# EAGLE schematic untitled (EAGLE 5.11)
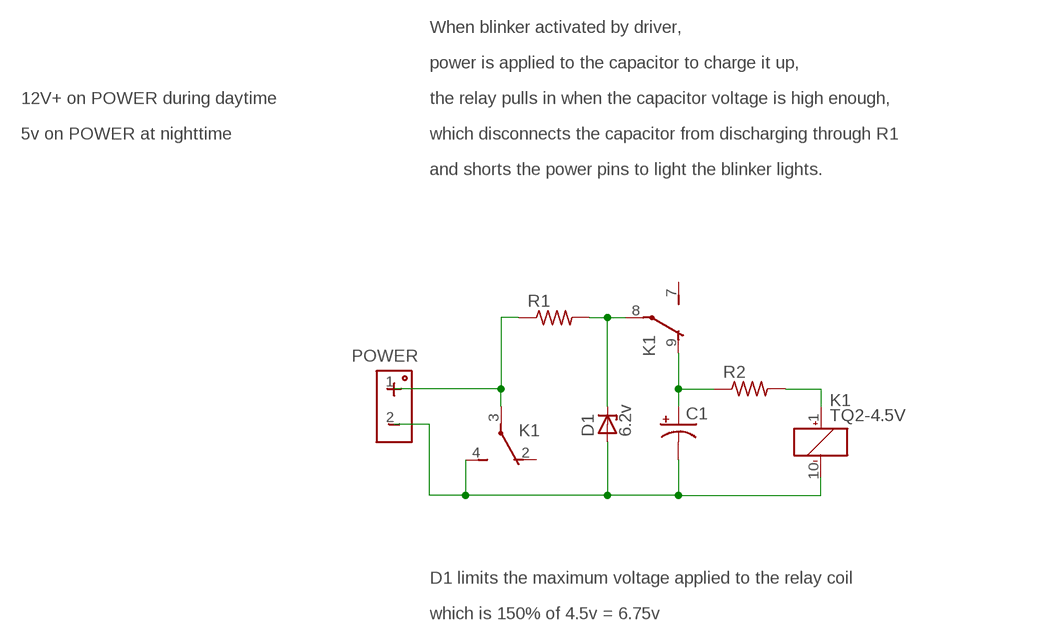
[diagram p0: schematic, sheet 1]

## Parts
C1  CPOL-USE2.5-5  [E2,5-5]
D1  6.2v  ZENER-DIODEZD-7.5  [ZDIO-7.5]
K1  TQ2-4.5V  [TQ2]
POWER  HEADER-POWER  [HEADER-POWER]
R1  R-US_0411/12  [0411/12]
R2  R-US_0411/12  [0411/12]

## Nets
N$1: K1.3(1:P) POWER.1 R1.1
N$2: C1.+ K1.9(2:O) R2.1
N$3: C1.- D1.A K1.4(1:S) K1.10(_:-) POWER.2
N$4: K1.1(_:+) R2.2
N$5: D1.C K1.8(2:P) R1.2
Unconnected: K1.2(1:O) K1.7(2:S)

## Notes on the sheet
- When blinker activated by driver,
- power is applied to the capacitor to charge it up,
- 12V+ on POWER during daytime | the relay pulls in when the capacitor voltage is high enough,
- 5v on POWER at nighttime | which disconnects the capacitor from discharging through R1
- and shorts the power pins to light the blinker lights.
- D1 limits the maximum voltage applied to the relay coil
- which is 150% of 4.5v = 6.75v

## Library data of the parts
C1 = resistor:CPOL-US: POLARIZED CAPACITOR, American symbol
D1 = diode:ZENER-DIODE: Z-Diode
K1 = relay:TQ2?*: LOW PROFILE 2 FORM C RELAY NAiS Source: http://www.mew-europe.com/.. en_ds_61020_0001.pdf Source: http://www.mew-europe.com/.. en_ds_61020_0004.pdf; MF: AROMAT/ MATSUSHITA; MPN: TQ2-4.5V; OC_FARNELL: 1163566; OC_NEWARK: 64K3199
POWER = trl:HEADER-POWER
R1 R2 = resistor:R-US_: RESISTOR, American symbol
